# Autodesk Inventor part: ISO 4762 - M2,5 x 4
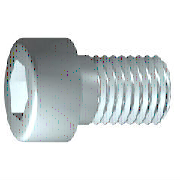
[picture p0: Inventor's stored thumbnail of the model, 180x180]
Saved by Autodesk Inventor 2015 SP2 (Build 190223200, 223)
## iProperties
IsCustomPart: 0
Created: 2012-02
Part Number: ISO 4762 - M2,5 x 4
Material: Edelstahl, 440C
Description: Innensechskantschraube
Document SubType Name: Modeling
Standard: ISO 4762
Designer: rYan
Standard Revision: 1998
Standards Organization: DIN
Language: de-DE
Size Designation: M2,5 x 4
Categories: <MemberInstance><Categories><Category DisplayName="Verbindungselemente" InternalName="e4da775c-781d-43d5-af7c-5136215cf5a6" Mnemonic="FSTN"><Category DisplayNam
Density: 7.75 g/cm^3
Appearance: Halbpoliert
Author: rYan
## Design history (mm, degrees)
sketch "Skizze1"
  geometry: L1 (-0.733, 0)-(4, 0); L2 (4, 0)-(4, 1.25); L3 (4, 1.25)-(1.125, 1.25); L4 (1.125, 1.25)-(0.849, 1.25); L5 (0.849, 1.25)-(0, 1.25); L6 (0, 1.25)-(0, 2.25); L7 (0, 2.25)-(-2.5, 2.25); L8 (-2.5, 2.25)-(-2.5, 1.155); L9 (-2.5, 1.155)-(-1.4, 1.155); L10 (-1.4, 1.155)-(-0.733, 0); L11 (-3.8, 0)-(5.3, 0) reference; L12 (0, -0.45)-(0, 2.7) reference; L13 (1.125, 1.25)-(0, 1.25)
  constraints: 22 end point, 6 parallel, 2 collinear, 2 perpendicular, 1 horizontal, 1 point on line
  dimensions: "d1" = 2.875 distance from line of L3.end L2 (= GEL); "d2" = 0.27615 distance of L4.end L3.end (computed from GAL); "d3" = 2.5 distance between parallel lines of L8 L6 (= KOH); "d4" = 1.1 distance of L8.end L9.end (= INTI); "d5" = 60 deg angle of L10 L1; "d6" = 2.5 diameter of L3 L1 (= GD); "d7" = 2.5 diameter of L5 L1 (= BDM); "d8" = 2.3094 diameter of L9 L1 (= 1.1547 x SW); "d9" = 4.5 diameter of L7 L1 (= KOD); "d26" = 4 distance between parallel lines of L12 L2 (= NLG)
revolve "Körper" sketch "Skizze1" stored, may be unused: angle "d10" = 90 deg
sketch "Skizze2"
  geometry: L1 (0, -3.15)-(0, 3.15) reference; L2 (-3.15, 0)-(3.15, 0) reference; L3 (1.155, 0)-(0.577, -1); L4 (0.577, -1)-(-0.577, -1); L5 (-0.577, -1)-(-1.155, 0); L6 (-1.155, 0)-(-0.577, 1); L7 (-0.577, 1)-(0.577, 1); L8 (0.577, 1)-(1.155, 0); 2 further points
  constraints: 12 end point, 1 coincident, 1 horizontal alignment, 1 point on line, 12 other
extrude "Loch" join sketch "Skizze2" stored distance "d11" = 10; taper "d12" = 0 deg
workplane "Work Plane1"
fillet "Fillet2" dims "d30" = 0.1 (= R)
body "Solid1"
fillet "Rundung1" dims "d17" = 0.25 (= RR)
feature "Gewinde" dims "d13" = 2.875 (= GEL), "d14" = 0
chamfer "Fase1" distance "d15" = 0.27605 (= -0.5 x SPD + 0.5 x GD); stored, may be unused: second distance "d16" = 0.27605 (= GUL), angle "d27" = 45 deg
other parameters: "GD" = 2.5 [user parameter; used in 2 equation terms], "NLG" = 4 [user parameter; used in 1 equation term], "GEL" = 2.875 [user parameter; used in 2 equation terms], "KOD" = 4.5 [user parameter; used in 1 equation term], "KOH" = 2.5 [user parameter; used in 1 equation term], "INTI" = 1.1 [user parameter; used in 1 equation term], "GAL" = 0.27605 (= 0.61345 x PTC) [user parameter; used in 1 equation term], "GUL" = 0.27605 (= 0.61345 x PTC) [user parameter; used in 1 equation term], "BDM" = 2.5 (= NND) [user parameter; used in 1 equation term], "SW" = 2 [user parameter; used in 2 equation terms], "RR" = 0.25 [user parameter; used in 1 equation term], "SPD" = 1.94789 (= NND - 1.2269 x PTC) [user parameter; used in 1 equation term], "d19" = 0, "d28" = 0, "d29" = 0, "R" = 0.1 [user parameter; used in 1 equation term], "TOA" = 30 deg [user parameter], "GD1" = 1.94789 (= THREADDIA - 1.2269 x PTC) [user parameter], "THREADDIA" = 2.5 [user parameter; used in 1 equation term], "FAWI" = 45 deg [user parameter], "TPU" = 22.22222 (computed from PTC) [user parameter], "PTC" = 0.45 [user parameter; used in 5 equation terms], "NND" = 2.5 [user parameter; used in 2 equation terms], "E0" = 2.31 (= 1.155 x SW) [user parameter]
